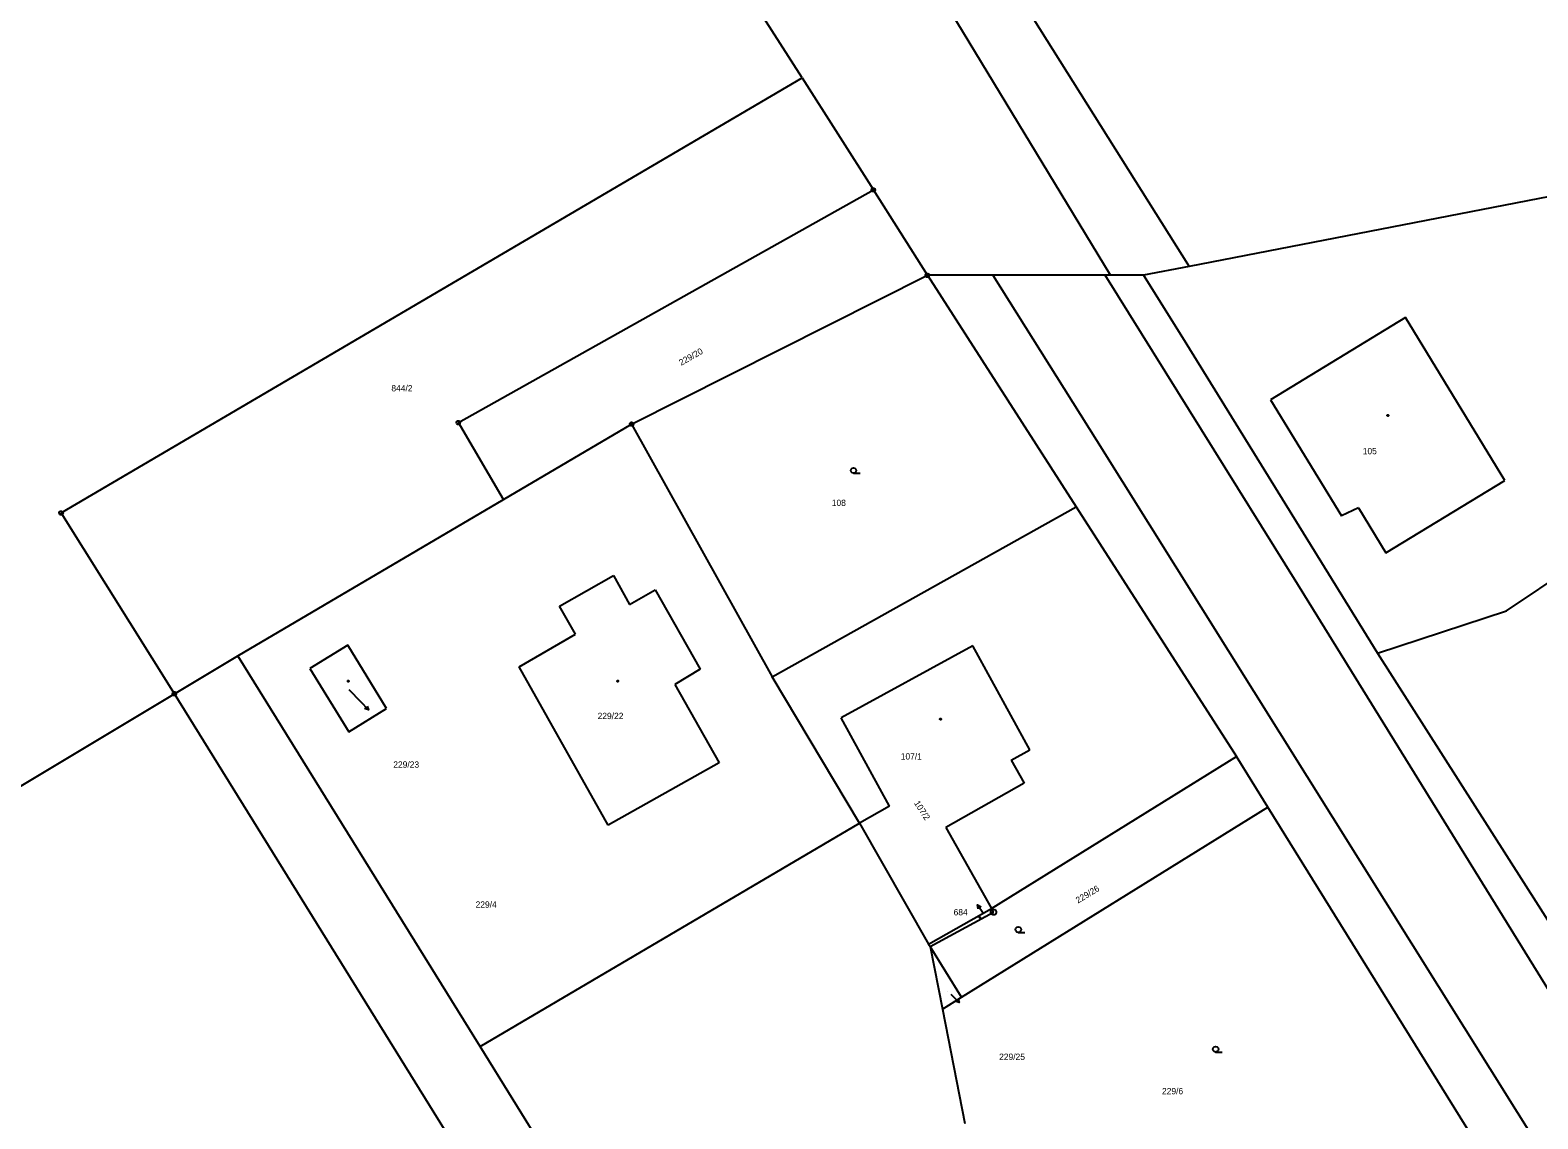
# Model space of a CAD drawing. Extents: x -871430 to -870620, y -1010094 to -1009649.
# Drawn here: x -871158.1 to -871056.6, y -1009793.5 to -1009720.2 of the extents above; entities that cross this region are included whole.
import ezdxf

# ---------------------------------------------------------------- set-up
doc = ezdxf.new("R2010")
doc.units = 0
for name, color, linetype in [('Vrstva 1', 7, 'Continuous'), ('Vrstva 2', 7, 'Continuous'), ('Vrstva 3', 7, 'Continuous'), ('Vrstva 4', 7, 'Continuous'), ('Vrstva 5', 7, 'Continuous'), ('Vrstva 7', 7, 'Continuous'), ('Vrstva 8', 7, 'Continuous')]:
    doc.layers.add(name, color=color, linetype=linetype)

msp = doc.modelspace()

# ---------------------------------------------------------------- linework, layer by layer
at = {"layer": 'Vrstva 1'}
for p, q in [((-871134.954, -1009648.909), (-871080.09, -1009736.13)), ((-871106.14, -1009723.45), (-871111.78, -1009714.59)), ((-871085.38, -1009736.72), (-871096.55, -1009718.3)), ((-871156, -1009752.72), (-871106.14, -1009723.45)), ((-871106.14, -1009723.45), (-871101.34, -1009730.98)), ((-871046.69, -1009729.64), (-871080.09, -1009736.13)), ((-871129.27, -1009746.64), (-871101.34, -1009730.98)), ((-871097.71, -1009736.73), (-871101.34, -1009730.98)), ((-871117.61, -1009746.74), (-871097.71, -1009736.73)), ((-871097.71, -1009736.73), (-871087.69, -1009752.31)), ((-871093.3, -1009736.73), (-871097.71, -1009736.73)), ((-871085.74, -1009736.72), (-871093.3, -1009736.73)), ((-871085.38, -1009736.72), (-871085.74, -1009736.72)), ((-871083.17, -1009736.73), (-871085.38, -1009736.72)), ((-871080.09, -1009736.13), (-871083.17, -1009736.73)), ((-871083.17, -1009736.73), (-871080.54, -1009740.92)), ((-871065.54, -1009739.56), (-871074.61, -1009745.1)), ((-871058.85, -1009750.53), (-871065.54, -1009739.56)), ((-871080.54, -1009740.92), (-871067.43, -1009762.15)), ((-871074.61, -1009745.1), (-871069.85, -1009752.91)), ((-871126.23, -1009751.82), (-871129.27, -1009746.64)), ((-871126.23, -1009751.82), (-871117.61, -1009746.74)), ((-871117.61, -1009746.74), (-871108.15, -1009763.74)), ((-871066.85, -1009755.4), (-871058.85, -1009750.53)), ((-871144.1, -1009762.34), (-871126.23, -1009751.82)), ((-871148.38, -1009764.88), (-871156, -1009752.72)), ((-871108.15, -1009763.74), (-871087.69, -1009752.31)), ((-871087.69, -1009752.31), (-871076.9, -1009769.11)), ((-871068.69, -1009752.37), (-871069.85, -1009752.91)), ((-871068.69, -1009752.37), (-871066.85, -1009755.4)), ((-871058.73, -1009759.3), (-871051.22, -1009754.24)), ((-871122.46, -1009758.98), (-871118.82, -1009756.92)), ((-871118.82, -1009756.92), (-871117.75, -1009758.87)), ((-871117.75, -1009758.87), (-871116.03, -1009757.89)), ((-871116.03, -1009757.89), (-871112.99, -1009763.23)), ((-871121.39, -1009760.88), (-871122.46, -1009758.98)), ((-871067.43, -1009762.15), (-871058.73, -1009759.3)), ((-871125.17, -1009763.07), (-871121.39, -1009760.88)), ((-871136.71, -1009761.62), (-871139.27, -1009763.19)), ((-871134.1, -1009765.88), (-871136.71, -1009761.62)), ((-871067.43, -1009762.15), (-871047.58, -1009793.3)), ((-871148.38, -1009764.88), (-871144.1, -1009762.34)), ((-871127.8, -1009788.62), (-871144.1, -1009762.34)), ((-871139.27, -1009763.19), (-871136.65, -1009767.45)), ((-871119.19, -1009773.72), (-871125.17, -1009763.07)), ((-871112.99, -1009763.23), (-871114.7, -1009764.25)), ((-871102.28, -1009773.6), (-871108.15, -1009763.74)), ((-871183.09, -1009785.71), (-871148.38, -1009764.88)), ((-871096.81, -1009848.03), (-871148.38, -1009764.88)), ((-871114.7, -1009764.25), (-871111.73, -1009769.54)), ((-871136.65, -1009767.45), (-871134.1, -1009765.88)), ((-871093.39, -1009779.33), (-871076.9, -1009769.11)), ((-871074.79, -1009772.51), (-871076.9, -1009769.11)), ((-871111.73, -1009769.54), (-871119.19, -1009773.72)), ((-871095.42, -1009785.3), (-871074.79, -1009772.51)), ((-871059.52, -1009797.14), (-871074.79, -1009772.51)), ((-871127.8, -1009788.62), (-871102.28, -1009773.6)), ((-871102.28, -1009773.6), (-871097.63, -1009781.73)), ((-871097.63, -1009781.73), (-871093.39, -1009779.33)), ((-871093.25, -1009779.58), (-871093.39, -1009779.33)), ((-871097.53, -1009781.9), (-871093.25, -1009779.58)), ((-871097.63, -1009781.73), (-871097.53, -1009781.9)), ((-871095.42, -1009785.3), (-871097.53, -1009781.9)), ((-871097.53, -1009781.9), (-871096.7, -1009786.1)), ((-871096.7, -1009786.1), (-871095.42, -1009785.3)), ((-871096.7, -1009786.1), (-871095.19, -1009793.79)), ((-871105.02, -1009825.37), (-871127.8, -1009788.62))]:
    msp.add_line(p, q, dxfattribs=at)
at = {"layer": 'Vrstva 3'}
for points in [[(-871102.68, -1009750.05), (-871102.775, -1009750.025), (-871102.842, -1009749.955), (-871102.868, -1009749.862), (-871102.842, -1009749.77), (-871102.775, -1009749.7), (-871102.68, -1009749.675), (-871102.585, -1009749.7), (-871102.518, -1009749.77), (-871102.492, -1009749.862), (-871102.518, -1009749.955), (-871102.585, -1009750.025), (-871102.68, -1009750.05), (-871102.242, -1009750.05)], [(-871091.59, -1009780.94), (-871091.685, -1009780.915), (-871091.752, -1009780.845), (-871091.778, -1009780.752), (-871091.752, -1009780.66), (-871091.685, -1009780.59), (-871091.59, -1009780.565), (-871091.495, -1009780.59), (-871091.428, -1009780.66), (-871091.402, -1009780.752), (-871091.428, -1009780.845), (-871091.495, -1009780.915), (-871091.59, -1009780.94), (-871091.152, -1009780.94)], [(-871078.31, -1009788.99), (-871078.405, -1009788.965), (-871078.472, -1009788.895), (-871078.498, -1009788.802), (-871078.472, -1009788.71), (-871078.405, -1009788.64), (-871078.31, -1009788.615), (-871078.215, -1009788.64), (-871078.148, -1009788.71), (-871078.122, -1009788.802), (-871078.148, -1009788.895), (-871078.215, -1009788.965), (-871078.31, -1009788.99), (-871077.872, -1009788.99)]]:
    msp.add_lwpolyline(points, dxfattribs=at)
at = {"layer": 'Vrstva 4'}
for p, q in [((-871093.3, -1009736.73), (-871086.33, -1009747.82)), ((-871072.78, -1009757.54), (-871085.74, -1009736.72)), ((-871086.33, -1009747.82), (-871017.56, -1009857.66)), ((-871020.6, -1009841.94), (-871072.78, -1009757.54)), ((-871094.64, -1009761.66), (-871103.5, -1009766.5)), ((-871090.81, -1009768.66), (-871094.64, -1009761.66)), ((-871100.26, -1009772.44), (-871103.5, -1009766.5)), ((-871092.08, -1009769.35), (-871090.81, -1009768.66)), ((-871092.08, -1009769.35), (-871091.2, -1009770.9)), ((-871091.2, -1009770.9), (-871096.47, -1009773.89)), ((-871100.26, -1009772.44), (-871102.28, -1009773.6)), ((-871096.47, -1009773.89), (-871093.39, -1009779.33))]:
    msp.add_line(p, q, dxfattribs=at)
at = {"layer": 'Vrstva 5'}
for points in [[(-871066.72, -1009746.118), (-871066.695, -1009746.122), (-871066.682, -1009746.145), (-871066.678, -1009746.16), (-871066.682, -1009746.182), (-871066.702, -1009746.2), (-871066.72, -1009746.202), (-871066.742, -1009746.195), (-871066.758, -1009746.18), (-871066.762, -1009746.16), (-871066.758, -1009746.138), (-871066.737, -1009746.12), (-871066.72, -1009746.118)], [(-871136.68, -1009763.998), (-871136.655, -1009764.003), (-871136.643, -1009764.025), (-871136.638, -1009764.04), (-871136.643, -1009764.062), (-871136.663, -1009764.08), (-871136.68, -1009764.082), (-871136.702, -1009764.075), (-871136.718, -1009764.06), (-871136.722, -1009764.04), (-871136.718, -1009764.018), (-871136.698, -1009764), (-871136.68, -1009763.998)], [(-871118.55, -1009763.998), (-871118.525, -1009764.003), (-871118.513, -1009764.025), (-871118.508, -1009764.04), (-871118.513, -1009764.062), (-871118.533, -1009764.08), (-871118.55, -1009764.082), (-871118.572, -1009764.075), (-871118.588, -1009764.06), (-871118.592, -1009764.04), (-871118.588, -1009764.018), (-871118.568, -1009764), (-871118.55, -1009763.998)], [(-871096.83, -1009766.548), (-871096.805, -1009766.552), (-871096.792, -1009766.575), (-871096.788, -1009766.59), (-871096.792, -1009766.612), (-871096.812, -1009766.63), (-871096.83, -1009766.632), (-871096.852, -1009766.625), (-871096.867, -1009766.61), (-871096.872, -1009766.59), (-871096.867, -1009766.568), (-871096.847, -1009766.55), (-871096.83, -1009766.548)], [(-871094.18, -1009779.912), (-871094.163, -1009779.915), (-871094.155, -1009779.93), (-871094.152, -1009779.94), (-871094.155, -1009779.955), (-871094.168, -1009779.967), (-871094.18, -1009779.968), (-871094.195, -1009779.963), (-871094.205, -1009779.953), (-871094.208, -1009779.94), (-871094.205, -1009779.925), (-871094.192, -1009779.913), (-871094.18, -1009779.912)]]:
    msp.add_lwpolyline(points, dxfattribs=at)
at = {"layer": 'Vrstva 7'}
for p, q in [((-871136.64, -1009764.59), (-871135.84, -1009765.43)), ((-871135.325, -1009765.975), (-871135.84, -1009765.43)), ((-871094.338, -1009779.081), (-871093.9, -1009779.69)), ((-871095.58, -1009785.651), (-871096.11, -1009785.12))]:
    msp.add_line(p, q, dxfattribs=at)
for points in [[(-871135.406, -1009765.708), (-871135.325, -1009765.975), (-871135.588, -1009765.879)], [(-871094.294, -1009779.357), (-871094.338, -1009779.081), (-871094.091, -1009779.211)], [(-871095.668, -1009785.386), (-871095.58, -1009785.651), (-871095.845, -1009785.562)]]:
    msp.add_lwpolyline(points, dxfattribs=at)
at = {"layer": 'Vrstva 8'}
for p, q in [((-871101.352, -1009730.98), (-871101.328, -1009730.98)), ((-871097.722, -1009736.73), (-871097.698, -1009736.73)), ((-871129.282, -1009746.64), (-871129.258, -1009746.64)), ((-871117.622, -1009746.74), (-871117.598, -1009746.74)), ((-871156.012, -1009752.72), (-871155.988, -1009752.72)), ((-871148.392, -1009764.88), (-871148.368, -1009764.88)), ((-871093.262, -1009779.58), (-871093.238, -1009779.58))]:
    msp.add_line(p, q, dxfattribs=at)
for points in [[(-871101.302, -1009730.86), (-871101.24, -1009730.908), (-871101.215, -1009730.98), (-871101.24, -1009731.052), (-871101.302, -1009731.1), (-871101.378, -1009731.1), (-871101.44, -1009731.052), (-871101.465, -1009730.98), (-871101.44, -1009730.908), (-871101.378, -1009730.86), (-871101.302, -1009730.86)], [(-871097.672, -1009736.61), (-871097.61, -1009736.658), (-871097.585, -1009736.73), (-871097.61, -1009736.802), (-871097.672, -1009736.85), (-871097.747, -1009736.85), (-871097.81, -1009736.802), (-871097.835, -1009736.73), (-871097.81, -1009736.658), (-871097.747, -1009736.61), (-871097.672, -1009736.61)], [(-871129.232, -1009746.52), (-871129.17, -1009746.568), (-871129.145, -1009746.64), (-871129.17, -1009746.712), (-871129.232, -1009746.76), (-871129.308, -1009746.76), (-871129.37, -1009746.712), (-871129.395, -1009746.64), (-871129.37, -1009746.568), (-871129.308, -1009746.52), (-871129.232, -1009746.52)], [(-871117.572, -1009746.62), (-871117.51, -1009746.668), (-871117.485, -1009746.74), (-871117.51, -1009746.812), (-871117.572, -1009746.86), (-871117.648, -1009746.86), (-871117.71, -1009746.812), (-871117.735, -1009746.74), (-871117.71, -1009746.668), (-871117.648, -1009746.62), (-871117.572, -1009746.62)], [(-871155.962, -1009752.6), (-871155.9, -1009752.648), (-871155.875, -1009752.72), (-871155.9, -1009752.792), (-871155.962, -1009752.84), (-871156.038, -1009752.84), (-871156.1, -1009752.792), (-871156.125, -1009752.72), (-871156.1, -1009752.648), (-871156.038, -1009752.6), (-871155.962, -1009752.6)], [(-871148.342, -1009764.76), (-871148.28, -1009764.808), (-871148.255, -1009764.88), (-871148.28, -1009764.952), (-871148.342, -1009765), (-871148.418, -1009765), (-871148.48, -1009764.952), (-871148.505, -1009764.88), (-871148.48, -1009764.808), (-871148.418, -1009764.76), (-871148.342, -1009764.76)], [(-871093.202, -1009779.4), (-871093.118, -1009779.448), (-871093.07, -1009779.532), (-871093.07, -1009779.63), (-871093.118, -1009779.715), (-871093.202, -1009779.762), (-871093.3, -1009779.762), (-871093.385, -1009779.715), (-871093.432, -1009779.63), (-871093.432, -1009779.532), (-871093.385, -1009779.448), (-871093.3, -1009779.4), (-871093.202, -1009779.4)]]:
    msp.add_lwpolyline(points, dxfattribs=at)

# ---------------------------------------------------------------- texts
at = {"layer": 'Vrstva 2'}
for s, height, rotation, p in [('229/20', 0.425, 29.67921, (-871114.273, -1009742.823)), ('229/26', 0.425, 31.2262, (-871087.57, -1009779.006)), ('107/2', 0.025, 32.88778, (-871093.875, -1009779.827))]:
    msp.add_text(s, height=height, rotation=rotation, dxfattribs=at).set_placement(p)
for s, height, p in [('844/2', 0.425, (-871133.777, -1009744.54)), ('105', 0.425, (-871068.412, -1009748.77)), ('108', 0.425, (-871104.142, -1009752.25)), ('229/23', 0.025, (-871136.709, -1009764.59)), ('229/22', 0.425, (-871119.9, -1009766.59)), ('107/1', 0.425, (-871099.502, -1009769.31)), ('229/4', 0.425, (-871128.111, -1009779.28)), ('229/25', 0.025, (-871096.379, -1009784.95)), ('229/6', 0.425, (-871081.921, -1009791.83))]:
    msp.add_text(s, height=height, dxfattribs=at).set_placement(p)
at = {"layer": 'Vrstva 7'}
for s, p in [('229/23', (-871133.65, -1009769.86)), ('229/25', (-871092.88, -1009789.52))]:
    msp.add_text(s, height=0.425, dxfattribs=at).set_placement(p)
msp.add_text('107/2', height=0.425, rotation=302.86549, dxfattribs=at).set_placement((-871098.624, -1009772.243))
at = {"layer": 'Vrstva 8'}
msp.add_text('684', height=0.425, dxfattribs=at).set_placement((-871095.944, -1009779.792))

doc.saveas('drawing.dxf')
